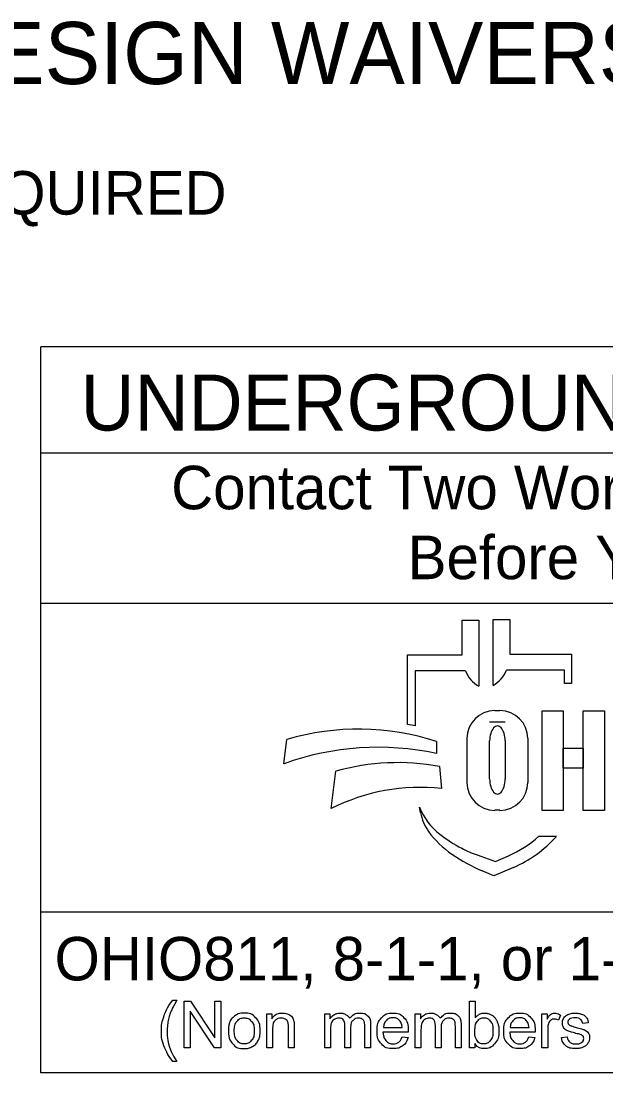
# Model space of a CAD drawing. Extents: x -13.1 to 43.1, y 0 to 22.
# Drawn here: x 2.914 to 4.796, y 2.143 to 5.529 of the extents above; entities that cross this region are included whole.
import ezdxf

# ---------------------------------------------------------------- set-up
doc = ezdxf.new("R2010")
doc.units = 0
doc.layers.add('SH_Data', color=7, linetype='Continuous')
doc.layers.add('SH_Text', color=7, linetype='Continuous')

msp = doc.modelspace()

# ---------------------------------------------------------------- linework, layer by layer
at = {"layer": 'SH_Data'}
for p, q in [((2.9775, 2.1428), (2.9775, 4.4803)), ((7.2275, 4.4803), (2.9775, 4.4803)), ((2.9775, 4.1387), (7.2275, 4.1387)), ((2.9775, 3.6553), (7.2275, 3.6553)), ((7.2275, 2.6607), (2.9775, 2.6607)), ((7.2275, 2.1428), (2.9775, 2.1428))]:
    msp.add_line(p, q, dxfattribs=at)
at = {"layer": 'SH_Text'}
for p, q in [((4.3335, 3.4883), (4.3335, 3.5998)), ((4.3335, 3.5998), (4.3872, 3.5998)), ((4.3872, 3.5998), (4.3872, 3.3877)), ((4.4329, 3.39), (4.4329, 3.6021)), ((4.4329, 3.6021), (4.4865, 3.6021)), ((4.4865, 3.6021), (4.4865, 3.4906)), ((4.1576, 3.2644), (4.1576, 3.4883)), ((4.1576, 3.4883), (4.3335, 3.4883)), ((4.4865, 3.4906), (4.6857, 3.4906)), ((4.6857, 3.4906), (4.6857, 3.3968)), ((4.1828, 3.4369), (4.1828, 3.26)), ((4.3439, 3.4369), (4.1828, 3.4369)), ((4.6625, 3.4392), (4.4761, 3.4392)), ((4.6625, 3.3968), (4.6625, 3.4392)), ((4.6857, 3.3968), (4.6625, 3.3968)), ((4.4385, 3.3091), (4.4551, 3.3091)), ((4.4718, 3.2721), (4.422, 3.2721)), ((4.3491, 3.0776), (4.3491, 3.2196)), ((4.5445, 3.2196), (4.5445, 3.0776)), ((3.7602, 3.1381), (3.7696, 3.2162)), ((4.2509, 3.2097), (4.2509, 3.1709)), ((4.422, 3.089), (4.422, 3.2114)), ((4.4718, 3.2114), (4.4718, 3.089)), ((4.2608, 3.1291), (4.2671, 3.0582)), ((3.912, 2.9936), (3.9267, 3.1137)), ((4.1997, 2.9807), (4.1967, 2.9986)), ((4.4551, 2.9882), (4.4385, 2.9882)), ((4.58, 2.9048), (4.6375, 2.9048)), ((4.3816, 2.8444), (4.441, 2.8239)), ((4.441, 2.8239), (4.4821, 2.8417)), ((4.435, 2.7769), (4.3976, 2.7934)), ((4.4983, 2.8044), (4.435, 2.7769))]:
    msp.add_line(p, q, dxfattribs=at)
for points in [[(4.591, 3.3081), (4.6589, 3.3081), (4.6589, 2.9881), (4.591, 2.9881)], [(4.7231, 3.3081), (4.7911, 3.3081), (4.7911, 2.9881), (4.7231, 2.9881)], [(4.6589, 3.1882), (4.7231, 3.1882), (4.7231, 3.1242), (4.6589, 3.1242)]]:
    msp.add_lwpolyline(points, close=True, dxfattribs=at)
for points in [[(3.4021, 2.3766), (3.4153, 2.3766)], [(3.4389, 2.2239), (3.4389, 2.3741), (3.4592, 2.3741), (3.5382, 2.2561), (3.5382, 2.3741), (3.5572, 2.3741), (3.5572, 2.2239), (3.5369, 2.2239), (3.4579, 2.3419), (3.4579, 2.2239), (3.4389, 2.2239)], [(4.3743, 2.2239), (4.3573, 2.2239), (4.3573, 2.3741), (4.3757, 2.3741), (4.3757, 2.3206)], [(3.7048, 2.2239), (3.7048, 2.3328), (3.7214, 2.3328), (3.7214, 2.3173)], [(3.8912, 2.2239), (3.8912, 2.3328), (3.9077, 2.3328), (3.9077, 2.3174)], [(4.1826, 2.2239), (4.1826, 2.3328), (4.1991, 2.3328), (4.1991, 2.3174)], [(4.5904, 2.2239), (4.5904, 2.3328), (4.607, 2.3328), (4.607, 2.3163)], [(4.6495, 2.3293), (4.643, 2.3122)], [(4.7394, 2.3046), (4.7213, 2.3022)], [(3.7233, 2.2833), (3.7233, 2.2239), (3.7048, 2.2239)], [(3.7932, 2.2908), (3.7932, 2.2239), (3.7748, 2.2239), (3.7748, 2.2901)], [(3.9097, 2.2803), (3.9097, 2.2239), (3.8912, 2.2239)], [(3.9743, 2.2871), (3.9743, 2.2239), (3.9559, 2.2239), (3.9559, 2.2946)], [(4.0388, 2.2986), (4.0388, 2.2239), (4.0203, 2.2239), (4.0203, 2.2924)], [(4.16, 2.2736), (4.0788, 2.2736)], [(4.0799, 2.2887), (4.1406, 2.2887)], [(4.201, 2.2803), (4.201, 2.2239), (4.1826, 2.2239)], [(4.2657, 2.2871), (4.2657, 2.2239), (4.2473, 2.2239), (4.2473, 2.2946)], [(4.3301, 2.2986), (4.3301, 2.2239), (4.3117, 2.2239), (4.3117, 2.2924)], [(4.568, 2.2736), (4.4868, 2.2736)], [(4.4879, 2.2887), (4.5486, 2.2887)], [(4.6088, 2.2809), (4.6088, 2.2239), (4.5904, 2.2239)], [(4.1404, 2.2591), (4.1595, 2.2567)], [(4.3743, 2.2375), (4.3743, 2.2239)], [(4.5484, 2.2591), (4.5675, 2.2567)], [(4.653, 2.2564), (4.6712, 2.2593)], [(3.4153, 2.1798), (3.4021, 2.1798)]]:
    msp.add_lwpolyline(points, dxfattribs=at)
for centre, radius, start, end in [((4.4353, 3.4736), 0.0985, 201.9296, 240.7469), ((4.3847, 3.476), 0.0985, 299.2531, 338.0704), ((4.4385, 3.2196), 0.0895, 90, 180), ((4.4551, 3.2196), 0.0895, 0, 90), ((4.0295, 2.4554), 0.8191, 79.2074, 81.0007), ((3.9997, 2.4302), 0.8191, 72.1402, 106.3144), ((4.0628, 2.2991), 0.8919, 77.8238, 109.8274), ((4.1267, 2.4094), 0.7322, 79.44, 105.8467), ((4.1987, 2.4262), 0.6357, 83.8248, 116.8021), ((4.4385, 3.0776), 0.0895, 180, 270), ((4.4551, 3.0776), 0.0895, 270, 0), ((4.3841, 3.0707), 0.2008, 201.0457, 232.5314), ((4.341, 3.0048), 0.1433, 189.6817, 216.0884), ((4.4747, 3.1022), 0.3088, 216.0884, 235.7167), ((4.5766, 3.3219), 0.5173, 232.5314, 241.794), ((4.3387, 3.1722), 0.3602, 293.4582, 312.0712), ((4.3387, 3.1722), 0.401, 293.4582, 317.8286), ((4.6412, 3.3465), 0.6044, 235.7167, 246.2325), ((4.4914, 3.1631), 0.3371, 241.794, 250.9821)]:
    msp.add_arc(centre, radius, start, end, dxfattribs=at)
for centre, start_param, end_param in [((4.4469, 3.2114), 4.712389, 7.853982), ((4.4469, 3.089), 1.570796, 4.712389)]:
    msp.add_ellipse(centre, major_axis=(0, 0.0484), ratio=0.514403, start_param=start_param, end_param=end_param, dxfattribs=at)
for points in [[(3.4021, 2.1798), (3.3869, 2.199), (3.3763, 2.2248), (3.3657, 2.2506), (3.3657, 2.2783), (3.3657, 2.3026), (3.3736, 2.325), (3.3829, 2.3509), (3.4021, 2.3766)], [(3.4153, 2.3766), (3.4029, 2.3553), (3.3989, 2.3462), (3.3927, 2.332), (3.3891, 2.3167), (3.3847, 2.2975), (3.3847, 2.2782), (3.3847, 2.2289), (3.4153, 2.1798)], [(3.5814, 2.2783), (3.5814, 2.3085), (3.5981, 2.3231), (3.6122, 2.3352), (3.6323, 2.3352), (3.6547, 2.3352), (3.669, 2.3205), (3.6832, 2.3058), (3.6832, 2.2799), (3.6832, 2.2589), (3.6769, 2.2469), (3.6706, 2.2348), (3.6586, 2.2282), (3.6466, 2.2215), (3.6323, 2.2215), (3.6095, 2.2215), (3.5954, 2.2362), (3.5814, 2.2508), (3.5814, 2.2783)], [(3.6003, 2.2783), (3.6003, 2.2574), (3.6094, 2.247), (3.6185, 2.2366), (3.6323, 2.2366), (3.646, 2.2366), (3.6551, 2.2471), (3.6642, 2.2575), (3.6642, 2.279), (3.6642, 2.2991), (3.6551, 2.3095), (3.6459, 2.3199), (3.6323, 2.3199), (3.6185, 2.3199), (3.6094, 2.3096), (3.6003, 2.2992), (3.6003, 2.2783)], [(3.7214, 2.3173), (3.7334, 2.3352), (3.756, 2.3352), (3.7659, 2.3352), (3.7741, 2.3316), (3.7823, 2.3281), (3.7864, 2.3224), (3.7905, 2.3166), (3.7922, 2.3087), (3.7932, 2.3036), (3.7932, 2.2908)], [(3.7748, 2.2901), (3.7748, 2.3013), (3.7726, 2.3069), (3.7705, 2.3125), (3.765, 2.3158), (3.7595, 2.3191), (3.7521, 2.3191), (3.7404, 2.3191), (3.7318, 2.3117), (3.7233, 2.3042), (3.7233, 2.2833)], [(3.9077, 2.3174), (3.9128, 2.3254), (3.9214, 2.3303), (3.9299, 2.3352), (3.9407, 2.3352), (3.9528, 2.3352), (3.9606, 2.3301), (3.9683, 2.3251), (3.9715, 2.3161), (3.9844, 2.3352), (4.0051, 2.3352), (4.0213, 2.3352), (4.03, 2.3262), (4.0388, 2.3172), (4.0388, 2.2986)], [(3.9559, 2.2946), (3.9559, 2.3069), (3.9514, 2.313), (3.9469, 2.3191), (3.9366, 2.3191), (3.9288, 2.3191), (3.9222, 2.315), (3.9156, 2.311), (3.9126, 2.3031), (3.9097, 2.2952), (3.9097, 2.2803)], [(4.0203, 2.2924), (4.0203, 2.3035), (4.0185, 2.3083), (4.0168, 2.3132), (4.012, 2.3162), (4.0073, 2.3191), (4.001, 2.3191), (3.9895, 2.3191), (3.9819, 2.3115), (3.9743, 2.3039), (3.9743, 2.2871)], [(4.1595, 2.2567), (4.155, 2.24), (4.1428, 2.2307), (4.1306, 2.2215), (4.1117, 2.2215), (4.0878, 2.2215), (4.0738, 2.2362), (4.0598, 2.2509), (4.0598, 2.2774), (4.0598, 2.3049), (4.074, 2.32), (4.0881, 2.3352), (4.1106, 2.3352), (4.1324, 2.3352), (4.1463, 2.3203), (4.1601, 2.3055), (4.1601, 2.2785), (4.1601, 2.2769), (4.16, 2.2736)], [(4.1406, 2.2887), (4.1394, 2.3025), (4.1337, 2.3094), (4.1249, 2.3201), (4.1108, 2.3201), (4.0981, 2.3201), (4.0894, 2.3115), (4.0808, 2.303), (4.0799, 2.2887)], [(4.1991, 2.3174), (4.2042, 2.3254), (4.2127, 2.3303), (4.2212, 2.3352), (4.2321, 2.3352), (4.2442, 2.3352), (4.2519, 2.3301), (4.2597, 2.3251), (4.2628, 2.3161), (4.2758, 2.3352), (4.2965, 2.3352), (4.3127, 2.3352), (4.3214, 2.3262), (4.3301, 2.3172), (4.3301, 2.2986)], [(4.2473, 2.2946), (4.2473, 2.3069), (4.2428, 2.313), (4.2383, 2.3191), (4.228, 2.3191), (4.2202, 2.3191), (4.2136, 2.315), (4.207, 2.311), (4.204, 2.3031), (4.201, 2.2952), (4.201, 2.2803)], [(4.3117, 2.2924), (4.3117, 2.3035), (4.3099, 2.3083), (4.3081, 2.3132), (4.3034, 2.3162), (4.2987, 2.3191), (4.2923, 2.3191), (4.2809, 2.3191), (4.2733, 2.3115), (4.2657, 2.3039), (4.2657, 2.2871)], [(4.3741, 2.2792), (4.3741, 2.2596), (4.3794, 2.2509), (4.3881, 2.2366), (4.4029, 2.2366), (4.415, 2.2366), (4.4238, 2.2471), (4.4326, 2.2576), (4.4326, 2.2784), (4.4326, 2.2998), (4.4241, 2.3099), (4.4157, 2.3201), (4.4038, 2.3201), (4.3917, 2.3201), (4.3829, 2.3096), (4.3741, 2.299), (4.3741, 2.2792)], [(4.3757, 2.3206), (4.3874, 2.3352), (4.4055, 2.3352), (4.4155, 2.3352), (4.4245, 2.3311), (4.4335, 2.3271), (4.4392, 2.3198), (4.445, 2.3124), (4.4483, 2.3021), (4.4516, 2.2918), (4.4516, 2.28), (4.4516, 2.252), (4.4378, 2.2368), (4.4239, 2.2215), (4.4046, 2.2215), (4.3853, 2.2215), (4.3743, 2.2375)], [(4.5675, 2.2567), (4.563, 2.24), (4.5508, 2.2307), (4.5386, 2.2215), (4.5196, 2.2215), (4.4958, 2.2215), (4.4818, 2.2362), (4.4678, 2.2509), (4.4678, 2.2774), (4.4678, 2.3049), (4.482, 2.32), (4.4961, 2.3352), (4.5186, 2.3352), (4.5404, 2.3352), (4.5543, 2.3203), (4.5681, 2.3055), (4.5681, 2.2785), (4.5681, 2.2769), (4.568, 2.2736)], [(4.5486, 2.2887), (4.5474, 2.3025), (4.5417, 2.3094), (4.5328, 2.3201), (4.5188, 2.3201), (4.5061, 2.3201), (4.4974, 2.3115), (4.4888, 2.303), (4.4879, 2.2887)], [(4.607, 2.3163), (4.6133, 2.3278), (4.6187, 2.3315), (4.6241, 2.3352), (4.6305, 2.3352), (4.6398, 2.3352), (4.6495, 2.3293)], [(4.643, 2.3122), (4.6363, 2.3162), (4.6295, 2.3162), (4.6235, 2.3162), (4.6187, 2.3125), (4.6139, 2.3089), (4.6119, 2.3024), (4.6088, 2.2926), (4.6088, 2.2809)], [(4.7213, 2.3022), (4.7201, 2.3106), (4.7142, 2.3153), (4.7083, 2.3201), (4.6975, 2.3201), (4.6848, 2.3201), (4.6794, 2.3159), (4.6739, 2.3116), (4.6739, 2.306), (4.6739, 2.3024), (4.6762, 2.2995), (4.6785, 2.2966), (4.6833, 2.2946), (4.686, 2.2936), (4.6996, 2.2899), (4.7192, 2.2847), (4.7269, 2.2813), (4.7347, 2.278), (4.7391, 2.2717), (4.7435, 2.2653), (4.7435, 2.2559), (4.7435, 2.2467), (4.7381, 2.2386), (4.7327, 2.2304), (4.7226, 2.226), (4.7124, 2.2215), (4.6996, 2.2215), (4.6784, 2.2215), (4.6672, 2.2303), (4.6561, 2.2391), (4.653, 2.2564)], [(4.6712, 2.2593), (4.6727, 2.2483), (4.6798, 2.2425), (4.6868, 2.2366), (4.6995, 2.2366), (4.7122, 2.2366), (4.7184, 2.2418), (4.7245, 2.247), (4.7245, 2.254), (4.7245, 2.2602), (4.7191, 2.2638), (4.7153, 2.2663), (4.7002, 2.2701), (4.6799, 2.2752), (4.672, 2.2789), (4.6642, 2.2827), (4.6601, 2.2893), (4.6561, 2.2959), (4.6561, 2.3038), (4.6561, 2.3111), (4.6594, 2.3173), (4.6628, 2.3235), (4.6685, 2.3276), (4.6728, 2.3308), (4.6803, 2.333), (4.6877, 2.3352), (4.6962, 2.3352), (4.709, 2.3352), (4.7187, 2.3315), (4.7284, 2.3278), (4.733, 2.3215), (4.7377, 2.3152), (4.7394, 2.3046)], [(4.0788, 2.2736), (4.0799, 2.2557), (4.089, 2.2462), (4.0981, 2.2366), (4.1117, 2.2366), (4.1219, 2.2366), (4.1291, 2.242), (4.1362, 2.2473), (4.1404, 2.2591)], [(4.4868, 2.2736), (4.4879, 2.2557), (4.497, 2.2462), (4.5061, 2.2366), (4.5197, 2.2366), (4.5299, 2.2366), (4.537, 2.242), (4.5442, 2.2473), (4.5484, 2.2591)]]:
    msp.add_open_spline(points, degree=3, dxfattribs=at)

# ---------------------------------------------------------------- texts
for s, height, p in [('ADA DESIGN WAIVERS', 0.2, (1.9944, 5.3256)), ('NONE REQUIRED', 0.14, (1.9944, 4.9056)), ('UNDERGROUND UTILITIES', 0.18, (3.1057, 4.2106)), ('Contact Two Working Days', 0.14, (3.3972, 3.9571)), ('Before You Dig', 0.14, (4.1583, 3.7321)), ('OHIO811, 8-1-1, or 1-800-362-2764', 0.14, (3.022, 2.4406))]:
    msp.add_text(s, height=height, dxfattribs=at).set_placement(p)

doc.saveas('drawing.dxf')
